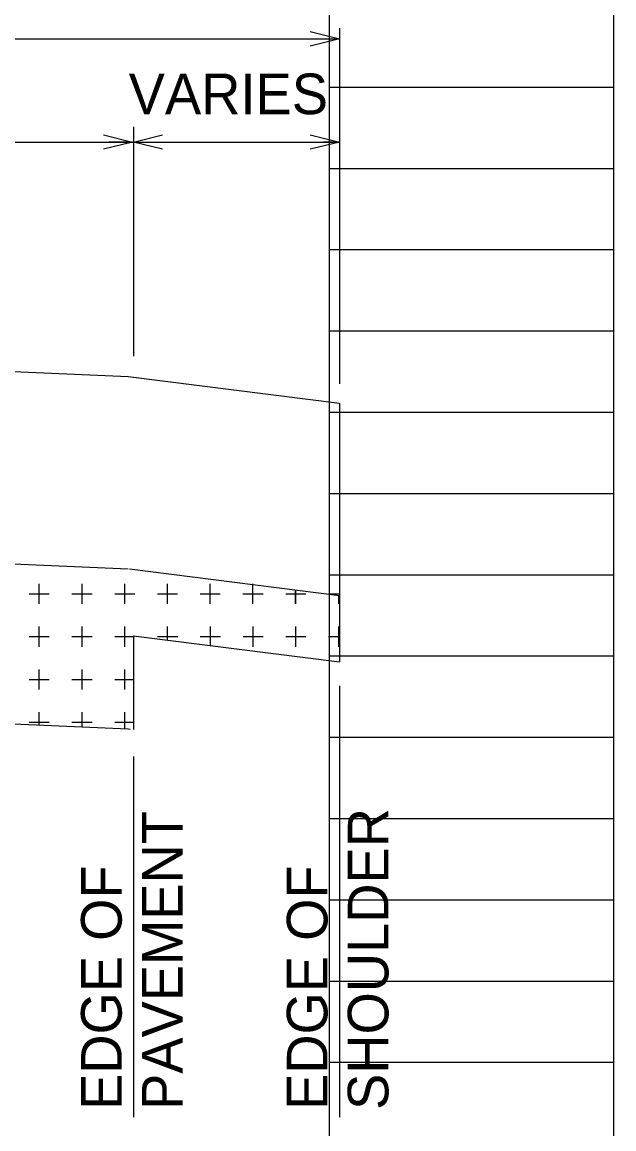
# Model space of a CAD drawing. Extents: x 0 to 34, y 0 to 22.
# Drawn here: x 22.622 to 24.66, y 2.431 to 6.244 of the extents above; entities that cross this region are included whole.
import ezdxf

# ---------------------------------------------------------------- set-up
doc = ezdxf.new("R2010")
doc.units = 0
doc.layers.add('SH_Data', color=7, linetype='Continuous')
doc.layers.add('TX_P_1', color=7, linetype='Continuous')

msp = doc.modelspace()

# ---------------------------------------------------------------- linework, layer by layer
at = {"layer": 'SH_Data'}
for p, q in [((23.68, 0.98), (23.68, 21.14)), ((24.66, 0.98), (24.66, 21.14)), ((23.68, 6.02), (24.66, 6.02)), ((23.68, 5.74), (24.66, 5.74)), ((23.68, 5.46), (24.66, 5.46)), ((23.68, 5.18), (24.66, 5.18)), ((23.68, 4.9), (24.66, 4.9)), ((23.68, 4.62), (24.66, 4.62)), ((23.68, 4.34), (24.66, 4.34)), ((23.68, 4.06), (24.66, 4.06)), ((23.68, 3.78), (24.66, 3.78)), ((23.68, 3.5), (24.66, 3.5)), ((23.68, 3.22), (24.66, 3.22)), ((23.68, 2.94), (24.66, 2.94)), ((23.68, 2.66), (24.66, 2.66))]:
    msp.add_line(p, q, dxfattribs=at)
at = {"layer": 'TX_P_1'}
for p, q in [((23.7143, 6.223), (23.7143, 5.3535)), ((21.5858, 6.1866), (23.7143, 6.1866)), ((23.0049, 5.8834), (23.0049, 5.0931)), ((23.7143, 5.8671), (23.7143, 4.9976)), ((21.5858, 5.8307), (23.0049, 5.8307)), ((23.0014, 5.8307), (22.9199, 5.8307)), ((23.0049, 5.8307), (23.7143, 5.8307)), ((23.7143, 5.8307), (23.6593, 5.8307)), ((23.7144, 4.9312), (23.7144, 4.2689)), ((23.1219, 4.2396), (23.1219, 4.3091)), ((23.2694, 4.2744), (23.2694, 4.3091)), ((23.4168, 4.2396), (23.4168, 4.3091)), ((22.6456, 4.2739), (22.6803, 4.2739)), ((22.6803, 4.2739), (22.6803, 4.3087)), ((22.6803, 4.2392), (22.6803, 4.2739)), ((22.6803, 4.2739), (22.7151, 4.2739)), ((22.7929, 4.2739), (22.8624, 4.2739)), ((22.8278, 4.2392), (22.8278, 4.3087)), ((22.9404, 4.2739), (22.9751, 4.2739)), ((22.9751, 4.2739), (22.9751, 4.3087)), ((22.9751, 4.2392), (22.9751, 4.2739)), ((22.9751, 4.2739), (23.0099, 4.2739)), ((23.0873, 4.2744), (23.1568, 4.2744)), ((23.2346, 4.2744), (23.2694, 4.2744)), ((23.2694, 4.2396), (23.2694, 4.2744)), ((23.2694, 4.2744), (23.3041, 4.2744)), ((23.3819, 4.2744), (23.4514, 4.2744)), ((23.5294, 4.2744), (23.5641, 4.2744)), ((23.5629, 4.2392), (23.5629, 4.2876)), ((23.5641, 4.2396), (23.5641, 4.2744)), ((23.5641, 4.2744), (23.5989, 4.2744)), ((23.5648, 4.2739), (23.5648, 4.2874)), ((23.6774, 4.2744), (23.7121, 4.2744)), ((23.7121, 4.2392), (23.7121, 4.2687)), ((23.7144, 4.2689), (23.7144, 4.0396)), ((22.6803, 4.0919), (22.6803, 4.1614)), ((22.8278, 4.1266), (22.8278, 4.1614)), ((22.9751, 4.0919), (22.9751, 4.1614)), ((23.1226, 4.1266), (23.1226, 4.1614)), ((23.2699, 4.0957), (23.2699, 4.1614)), ((23.4173, 4.1266), (23.4173, 4.1614)), ((23.5648, 4.0919), (23.5648, 4.1614)), ((23.7121, 4.1266), (23.7121, 4.1614)), ((22.6456, 4.1266), (22.7151, 4.1266)), ((22.7929, 4.1266), (22.8278, 4.1266)), ((22.8278, 4.0919), (22.8278, 4.1266)), ((22.8278, 4.1266), (22.8624, 4.1266)), ((22.9404, 4.1266), (23.0049, 4.1266)), ((23.0049, 4.1294), (23.0049, 3.8066)), ((23.0878, 4.1266), (23.1226, 4.1266)), ((23.1226, 4.1146), (23.1226, 4.1266)), ((23.1226, 4.1266), (23.1573, 4.1266)), ((23.2353, 4.1266), (23.3048, 4.1266)), ((23.3826, 4.1266), (23.4173, 4.1266)), ((23.4173, 4.0919), (23.4173, 4.1266)), ((23.4173, 4.1266), (23.4521, 4.1266)), ((23.5299, 4.1266), (23.5994, 4.1266)), ((23.6774, 4.1266), (23.7121, 4.1266)), ((23.7121, 4.0919), (23.7121, 4.1266)), ((23.7121, 4.1266), (23.7144, 4.1266)), ((22.6803, 3.9792), (22.6803, 4.0139)), ((22.8278, 3.9444), (22.8278, 4.0139)), ((22.9751, 3.9792), (22.9751, 4.0139)), ((22.6456, 3.9792), (22.6803, 3.9792)), ((22.6803, 3.9444), (22.6803, 3.9792)), ((22.6803, 3.9792), (22.7151, 3.9792)), ((22.7929, 3.9792), (22.8624, 3.9792)), ((22.9404, 3.9792), (22.9751, 3.9792)), ((22.9751, 3.9444), (22.9751, 3.9792)), ((22.9751, 3.9792), (23.0049, 3.9792)), ((23.7144, 3.9574), (23.7144, 2.4714)), ((22.6803, 3.8222), (22.6803, 3.8666)), ((22.8278, 3.8317), (22.8278, 3.8666)), ((22.9751, 3.8094), (22.9751, 3.8666)), ((22.6456, 3.8317), (22.7151, 3.8317)), ((22.7929, 3.8317), (22.8278, 3.8317)), ((22.8278, 3.8157), (22.8278, 3.8317)), ((22.8278, 3.8317), (22.8624, 3.8317)), ((22.9404, 3.8317), (23.0049, 3.8317)), ((23.0049, 3.7131), (23.0049, 2.4714))]:
    msp.add_line(p, q, dxfattribs=at)
for points in [[(23.6141, 6.2118), (23.7143, 6.1866), (23.6141, 6.1616)], [(22.9013, 5.8559), (23.0014, 5.8307), (22.9013, 5.8057)], [(23.1053, 5.8057), (23.0049, 5.8307), (23.1053, 5.8559)], [(23.6141, 5.8559), (23.7143, 5.8307), (23.6141, 5.8057)], [(21.5858, 5.0841), (22.9864, 5.0234), (23.7144, 4.9312)], [(21.5859, 4.4214), (22.9864, 4.3607)], [(22.9913, 4.3606), (23.7144, 4.2689)], [(23.0049, 4.1294), (23.7144, 4.0396)], [(20.6324, 3.9109), (22.9864, 3.8089), (22.9939, 3.8079)]]:
    msp.add_lwpolyline(points, dxfattribs=at)

# ---------------------------------------------------------------- texts
msp.add_text('VARIES', height=0.14, dxfattribs=at).set_placement((22.9886, 5.9267))
for s, p in [('PAVEMENT', (23.1744, 2.4959)), ('SHOULDER', (23.8833, 2.4959)), ('EDGE OF', (22.9644, 2.4959)), ('EDGE OF', (23.6733, 2.4959))]:
    msp.add_text(s, height=0.14, rotation=90, dxfattribs=at).set_placement(p)

doc.saveas('drawing.dxf')
